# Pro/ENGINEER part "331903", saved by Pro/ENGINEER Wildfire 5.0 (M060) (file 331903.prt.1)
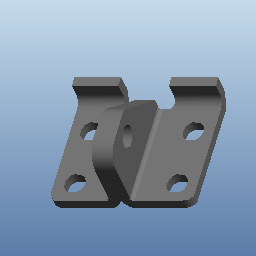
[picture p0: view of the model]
Units: PSOLunit; MM, KILOGRAM, SECS

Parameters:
  NN = "331903"
  NT = "Stainless Steel - Latch Clamps - 331-RSS Series - Base"
  NB = "331903"
  NBSYN = "$PN."
  LINA = "331903"
  S1 = "331-SS"
  S = "331-rss"
  PN = "331903"
  SUPPLIER = "DESTACO"
  ARTICLENO = "331903"
  BOMINFO = "331903"
  CREATOR = "CADENAS GmbH"

Other parameters: A1, A2, A3, A4, A5, A6, A7, A8, A9, B1, B2, B3, B4, B5, B6, B7, B8, B9, SURF_AREA, MASS

Other named items: COORD, DEF-PLANE-AXIS, DEF-PLANE-AXIS-INV, CS0, ITEM, ITEM_1, ITEM_2, ITEM_3, CS4, CS5, CS6, CS7, CS8, BASE_TO_HANDLE_CSYS, BASE_TO_PLATE_CSYS, CONN, MASS, RIGHT, TOP, FRONT, BASE_TO_HANDLE_XPLN, BASE_TO_HANDLE_YPLN, BASE_TO_HANDLE_ZPLN, BASE_TO_PLATE_XPLN, BASE_TO_PLATE_YPLN, BASE_TO_PLATE_ZPLN, BASE_TO_HANDLE_ZAXS, BASE_TO_PLATE_ZAXS, CS1, CS2, CS3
